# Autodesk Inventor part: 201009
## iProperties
Created: 2007-10
Part Number: 201009
Document SubType Name: Modeling
Designer: MM
Density: 7.85 g/cm^3
Mass: 1039.33 g
Surface Area: 1235.3 cm^2
Volume: 132.398 cm^3
Material: Steel
Description: TOP FRAME RIGHT SIDE PLATE
Component Category: Lower Component
Author: MM
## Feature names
1. Extrusion1
2. Extrusion2
3. Fillet1
4. Extrusion3
5. Extrusion4
6. Fillet4
7. Fillet5
8. Fillet6
9. Fillet7
10. Extrusion9
11. Chamfer2
12. Chamfer3
13. Fillet13
14. Fillet14
15. Extrusion10
16. Chamfer4
17. Fillet15
18. Fillet16
19. Fillet8
20. Shell1
21. Extrusion5
22. Extrusion6
23. Extrusion7
24. Extrusion8
25. Fillet9
26. Fillet10
27. Fillet11
28. Fillet12
29. Extrusion11
30. Fillet17
31. Fillet18
32. Extrusion12
33. Extrusion13
34. Fillet19
35. Fillet20
36. Extrusion14
37. Extrusion15
38. Fillet21
39. Fillet22
40. Fillet23
41. Hole1
42. Hole2
43. Hole3
44. Hole4
45. Extrusion17
46. Extrusion18
47. Extrusion19
